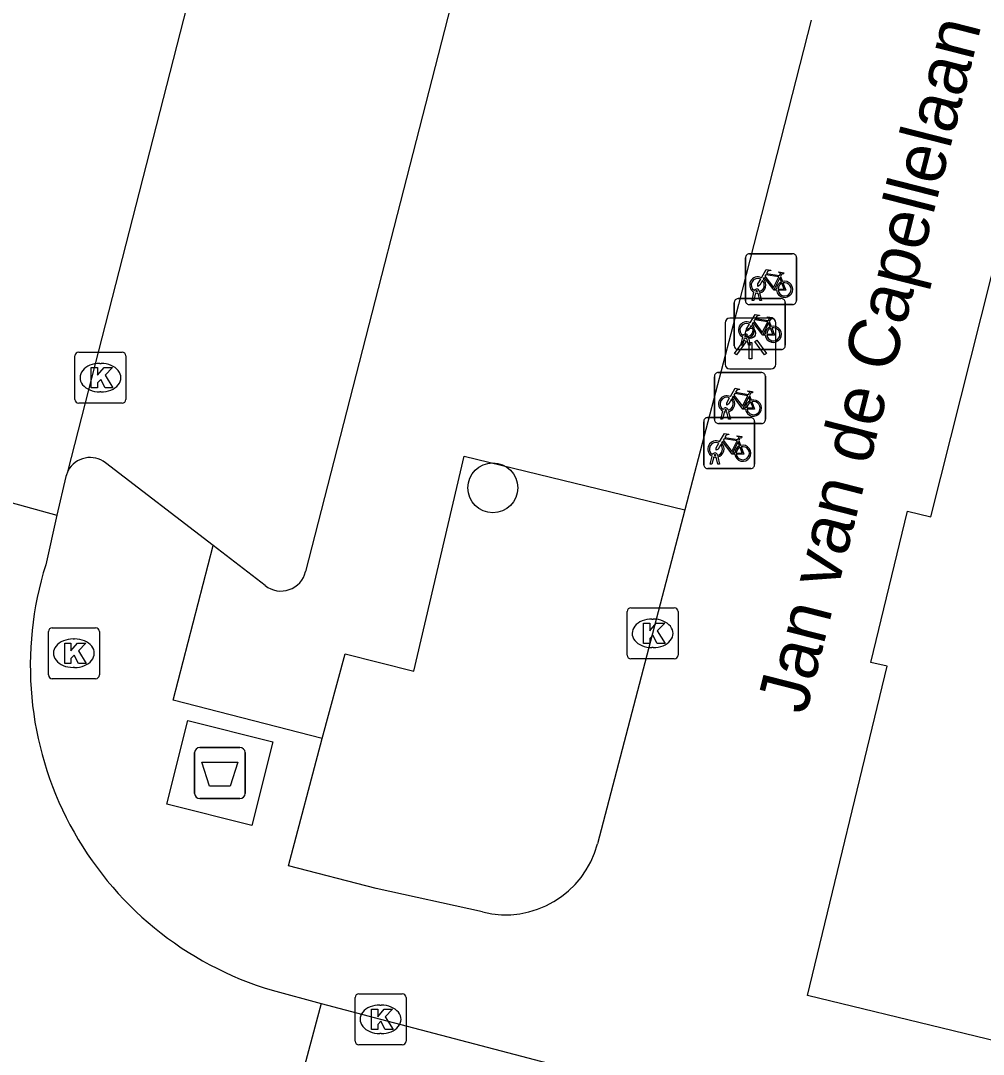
# Model space of a CAD drawing. Extents: x 163686 to 164493, y 382719 to 383870.
# Drawn here: x 164060.01 to 164078.91, y 383235.29 to 383255.57 of the extents above; entities that cross this region are included whole.
import ezdxf

# ---------------------------------------------------------------- set-up
doc = ezdxf.new("R2010")
doc.units = 0
for name, color, linetype in [('IMGEO_Afval_apart_plaats', 7, 'Continuous'), ('IMGEO_Boom', 7, 'Continuous'), ('IMGEO_Fietsenrek', 7, 'Continuous'), ('IMGEO_Groenvoorziening', 7, 'Continuous'), ('IMGEO_Kolk', 7, 'Continuous'), ('IMGEO_Lichtpunt', 7, 'Continuous'), ('IMGEO_Openbare_ruimte_label', 7, 'Continuous'), ('IMGEO_Pand', 7, 'Continuous'), ('IMGEO_Parkeervlak_open', 7, 'Continuous'), ('IMGEO_Rijbaan_lokaal_open', 7, 'Continuous'), ('IMGEO_Voetpad_gesloten', 7, 'Continuous'), ('IMGEO_Voetpad_open', 7, 'Continuous')]:
    doc.layers.add(name, color=color, linetype=linetype)

msp = doc.modelspace()

# ---------------------------------------------------------------- linework, layer by layer
at = {"layer": 'IMGEO_Afval_apart_plaats'}
for p, q in [((164063.428, 383240.407), (164063.428, 383241.207)), ((164063.428, 383241.207), (164063.428, 383240.407)), ((164063.528, 383241.307), (164064.318, 383241.307)), ((164064.318, 383241.307), (164063.528, 383241.307)), ((164064.418, 383241.207), (164064.418, 383240.407)), ((164064.418, 383240.407), (164064.418, 383241.207)), ((164064.318, 383240.307), (164063.528, 383240.307)), ((164063.528, 383240.307), (164064.318, 383240.307))]:
    msp.add_line(p, q, dxfattribs=at)
msp.add_lwpolyline([(164063.571, 383241.021), (164064.275, 383241.021), (164064.126, 383240.551), (164063.72, 383240.551), (164063.571, 383241.021)], dxfattribs=at)
for centre, start, end in [((164063.528, 383241.207), 90, 180), ((164063.528, 383241.207), 90, 180), ((164064.318, 383241.207), 0, 90), ((164064.318, 383241.207), 360, 90), ((164063.528, 383240.407), 180, 270), ((164063.528, 383240.407), 180, 270), ((164064.318, 383240.407), 270, 0), ((164064.318, 383240.407), 270, 0)]:
    msp.add_arc(centre, 0.1, start, end, dxfattribs=at)
at = {"layer": 'IMGEO_Boom'}
msp.add_circle((164069.28, 383246.4), 0.489, dxfattribs=at)
at = {"layer": 'IMGEO_Fietsenrek'}
for p, q in [((164074.315, 383250.995), (164075.156, 383250.995)), ((164075.156, 383250.995), (164074.315, 383250.995)), ((164074.24, 383250.07), (164074.24, 383250.911)), ((164074.24, 383250.911), (164074.24, 383250.07)), ((164075.24, 383250.92), (164075.24, 383250.079)), ((164075.24, 383250.079), (164075.24, 383250.92)), ((164074.927, 383250.544), (164074.963, 383250.449)), ((164074.367, 383250.079), (164074.406, 383250.239)), ((164074.436, 383250.227), (164074.401, 383250.079)), ((164074.478, 383250.251), (164074.477, 383250.255)), ((164074.519, 383250.079), (164074.485, 383250.221)), ((164074.509, 383250.262), (164074.51, 383250.255)), ((164074.517, 383250.225), (164074.552, 383250.079)), ((164074.019, 383249.188), (164074.019, 383250.029)), ((164074.019, 383250.029), (164074.019, 383249.188)), ((164074.094, 383250.113), (164074.935, 383250.113)), ((164074.935, 383250.113), (164074.094, 383250.113)), ((164075.165, 383249.995), (164074.324, 383249.995)), ((164074.324, 383249.995), (164075.165, 383249.995)), ((164074.401, 383250.079), (164074.367, 383250.079)), ((164074.552, 383250.079), (164074.519, 383250.079)), ((164075.019, 383250.038), (164075.019, 383249.197)), ((164075.019, 383249.197), (164075.019, 383250.038)), ((164074.706, 383249.662), (164074.742, 383249.567)), ((164074.146, 383249.197), (164074.185, 383249.357)), ((164074.215, 383249.345), (164074.18, 383249.197)), ((164074.257, 383249.369), (164074.256, 383249.373)), ((164074.298, 383249.197), (164074.264, 383249.339)), ((164074.288, 383249.38), (164074.289, 383249.373)), ((164074.296, 383249.343), (164074.331, 383249.197)), ((164074.18, 383249.197), (164074.146, 383249.197)), ((164074.331, 383249.197), (164074.298, 383249.197)), ((164074.944, 383249.113), (164074.103, 383249.113)), ((164074.103, 383249.113), (164074.944, 383249.113)), ((164073.63, 383247.739), (164073.63, 383248.58)), ((164073.63, 383248.58), (164073.63, 383247.739)), ((164073.705, 383248.664), (164074.546, 383248.664)), ((164074.546, 383248.664), (164073.705, 383248.664)), ((164074.63, 383248.589), (164074.63, 383247.748)), ((164074.63, 383247.748), (164074.63, 383248.589)), ((164074.317, 383248.213), (164074.353, 383248.118)), ((164073.757, 383247.748), (164073.796, 383247.908)), ((164073.868, 383247.92), (164073.867, 383247.924)), ((164073.899, 383247.931), (164073.9, 383247.924)), ((164073.419, 383246.854), (164073.419, 383247.695)), ((164073.419, 383247.695), (164073.419, 383246.854)), ((164073.494, 383247.779), (164074.335, 383247.779)), ((164074.335, 383247.779), (164073.494, 383247.779)), ((164073.791, 383247.748), (164073.757, 383247.748)), ((164073.826, 383247.896), (164073.791, 383247.748)), ((164073.909, 383247.748), (164073.875, 383247.89)), ((164073.907, 383247.894), (164073.942, 383247.748)), ((164073.942, 383247.748), (164073.909, 383247.748)), ((164074.419, 383247.704), (164074.419, 383246.863)), ((164074.419, 383246.863), (164074.419, 383247.704)), ((164074.555, 383247.664), (164073.714, 383247.664)), ((164073.714, 383247.664), (164074.555, 383247.664)), ((164074.106, 383247.328), (164074.142, 383247.233)), ((164073.546, 383246.863), (164073.585, 383247.023)), ((164073.615, 383247.011), (164073.58, 383246.863)), ((164073.657, 383247.035), (164073.656, 383247.039)), ((164073.698, 383246.863), (164073.664, 383247.005)), ((164073.688, 383247.046), (164073.689, 383247.039)), ((164073.696, 383247.009), (164073.731, 383246.863)), ((164074.344, 383246.779), (164073.503, 383246.779)), ((164073.503, 383246.779), (164074.344, 383246.779)), ((164073.58, 383246.863), (164073.546, 383246.863)), ((164073.731, 383246.863), (164073.698, 383246.863))]:
    msp.add_line(p, q, dxfattribs=at)
for points in [[(164074.553, 383250.521), (164074.648, 383250.685), (164074.734, 383250.671), (164074.736, 383250.662), (164074.68, 383250.651), (164074.653, 383250.606), (164074.909, 383250.565)], [(164074.896, 383250.54), (164074.639, 383250.581), (164074.622, 383250.552), (164074.789, 383250.332), (164074.896, 383250.54)], [(164074.909, 383250.565), (164074.934, 383250.614), (164074.928, 383250.618), (164074.905, 383250.622), (164074.893, 383250.629), (164074.892, 383250.632), (164074.894, 383250.637), (164074.989, 383250.622), (164074.991, 383250.612), (164074.981, 383250.599), (164074.969, 383250.593), (164074.955, 383250.599), (164074.927, 383250.544)], [(164074.574, 383250.469), (164074.522, 383250.379), (164074.482, 383250.354), (164074.483, 383250.401), (164074.538, 383250.495)], [(164074.849, 383250.277), (164074.799, 383250.277), (164074.608, 383250.528), (164074.589, 383250.496)], [(164074.944, 383250.442), (164074.914, 383250.519), (164074.805, 383250.301), (164074.848, 383250.301)], [(164074.878, 383250.301), (164074.998, 383250.3), (164074.954, 383250.414)], [(164074.974, 383250.421), (164075.029, 383250.276), (164074.879, 383250.276)], [(164074.332, 383249.639), (164074.427, 383249.803), (164074.513, 383249.789), (164074.515, 383249.78), (164074.459, 383249.769), (164074.432, 383249.724), (164074.688, 383249.683)], [(164074.688, 383249.683), (164074.713, 383249.732), (164074.707, 383249.736), (164074.684, 383249.74), (164074.672, 383249.747), (164074.671, 383249.75), (164074.673, 383249.755), (164074.768, 383249.74), (164074.77, 383249.73), (164074.76, 383249.717), (164074.748, 383249.711), (164074.734, 383249.717), (164074.706, 383249.662)], [(164074.353, 383249.587), (164074.301, 383249.497), (164074.261, 383249.472), (164074.262, 383249.519), (164074.317, 383249.613)], [(164074.628, 383249.395), (164074.578, 383249.395), (164074.387, 383249.646), (164074.368, 383249.614)], [(164074.675, 383249.658), (164074.418, 383249.699), (164074.401, 383249.67), (164074.568, 383249.45), (164074.675, 383249.658)], [(164074.723, 383249.56), (164074.693, 383249.637), (164074.584, 383249.419), (164074.627, 383249.419)], [(164074.657, 383249.419), (164074.777, 383249.418), (164074.733, 383249.532)], [(164074.753, 383249.539), (164074.808, 383249.394), (164074.658, 383249.394)], [(164073.943, 383248.19), (164074.038, 383248.354), (164074.124, 383248.34), (164074.126, 383248.331), (164074.07, 383248.32), (164074.043, 383248.275), (164074.299, 383248.234)], [(164074.299, 383248.234), (164074.324, 383248.283), (164074.318, 383248.287), (164074.295, 383248.291), (164074.283, 383248.298), (164074.282, 383248.301), (164074.284, 383248.306), (164074.379, 383248.291), (164074.381, 383248.281), (164074.371, 383248.268), (164074.359, 383248.262), (164074.345, 383248.268), (164074.317, 383248.213)], [(164073.964, 383248.138), (164073.912, 383248.048), (164073.872, 383248.023), (164073.873, 383248.07), (164073.928, 383248.164)], [(164074.239, 383247.946), (164074.189, 383247.946), (164073.998, 383248.197), (164073.979, 383248.165)], [(164074.286, 383248.209), (164074.029, 383248.25), (164074.012, 383248.221), (164074.179, 383248.001), (164074.286, 383248.209)], [(164074.334, 383248.111), (164074.304, 383248.188), (164074.195, 383247.97), (164074.238, 383247.97)], [(164074.268, 383247.97), (164074.388, 383247.969), (164074.344, 383248.083)], [(164074.364, 383248.09), (164074.419, 383247.945), (164074.269, 383247.945)], [(164073.732, 383247.305), (164073.827, 383247.469), (164073.913, 383247.455), (164073.915, 383247.446), (164073.859, 383247.435), (164073.832, 383247.39), (164074.088, 383247.349)], [(164074.028, 383247.061), (164073.978, 383247.061), (164073.787, 383247.312), (164073.768, 383247.28)], [(164074.075, 383247.324), (164073.818, 383247.365), (164073.801, 383247.336), (164073.968, 383247.116), (164074.075, 383247.324)], [(164074.123, 383247.226), (164074.093, 383247.303), (164073.984, 383247.085), (164074.027, 383247.085)], [(164074.088, 383247.349), (164074.113, 383247.398), (164074.107, 383247.402), (164074.084, 383247.406), (164074.072, 383247.413), (164074.071, 383247.416), (164074.073, 383247.421), (164074.168, 383247.406), (164074.17, 383247.396), (164074.16, 383247.383), (164074.148, 383247.377), (164074.134, 383247.383), (164074.106, 383247.328)], [(164073.753, 383247.253), (164073.701, 383247.163), (164073.661, 383247.138), (164073.662, 383247.185), (164073.717, 383247.279)], [(164074.057, 383247.085), (164074.177, 383247.084), (164074.133, 383247.198)], [(164074.153, 383247.205), (164074.208, 383247.06), (164074.058, 383247.06)]]:
    msp.add_lwpolyline(points, dxfattribs=at)
for centre, radius, start, end in [((164074.318, 383250.917), 0.0779, 92.4484, 184.2845), ((164074.318, 383250.917), 0.0779, 92.4484, 184.2845), ((164075.162, 383250.917), 0.0779, 2.4484, 94.2845), ((164075.162, 383250.917), 0.0779, 2.4484, 94.2845), ((164074.48, 383250.38), 0.159, 62.6766, 242.1369), ((164074.48, 383250.38), 0.129, 63.3192, 238.903), ((164074.48, 383250.38), 0.129, 283.6043, 43.4302), ((164074.48, 383250.38), 0.159, 283.5766, 46.6042), ((164075.007, 383250.296), 0.159, 113.3408, 178.3217), ((164075.007, 383250.296), 0.159, 187.0065, 105.7708), ((164075.007, 383250.296), 0.129, 113.923, 177.9556), ((164075.007, 383250.296), 0.129, 188.6715, 104.5883), ((164074.46, 383250.251), 0.0499, 12.8025, 158.6934), ((164074.48, 383250.38), 0.159, 253.9967, 271.7867), ((164074.46, 383250.251), 0.0174, 12.8025, 163.4502), ((164074.48, 383250.38), 0.129, 253.415, 269.0204), ((164074.097, 383250.035), 0.0779, 92.4484, 184.2845), ((164074.097, 383250.035), 0.0779, 92.4484, 184.2845), ((164074.318, 383250.073), 0.0779, 182.4484, 274.2845), ((164074.318, 383250.073), 0.0779, 182.4484, 274.2845), ((164074.941, 383250.035), 0.0779, 2.4484, 94.2845), ((164074.941, 383250.035), 0.0779, 2.4484, 94.2845), ((164075.162, 383250.073), 0.0779, 272.4484, 4.2845), ((164075.162, 383250.073), 0.0779, 272.4484, 4.2845), ((164074.259, 383249.498), 0.159, 62.6766, 242.1369), ((164074.259, 383249.498), 0.129, 63.3192, 238.903), ((164074.259, 383249.498), 0.129, 283.6043, 43.4302), ((164074.259, 383249.498), 0.159, 283.5766, 46.6042), ((164074.786, 383249.414), 0.159, 113.3408, 178.3217), ((164074.786, 383249.414), 0.159, 187.0065, 105.7708), ((164074.786, 383249.414), 0.129, 113.923, 177.9556), ((164074.786, 383249.414), 0.129, 188.6715, 104.5883), ((164074.239, 383249.369), 0.0499, 12.8025, 158.6934), ((164074.259, 383249.498), 0.159, 253.9967, 271.7867), ((164074.239, 383249.369), 0.0174, 12.8025, 163.4502), ((164074.259, 383249.498), 0.129, 253.415, 269.0204), ((164074.097, 383249.191), 0.0779, 182.4484, 274.2845), ((164074.097, 383249.191), 0.0779, 182.4484, 274.2845), ((164074.941, 383249.191), 0.0779, 272.4484, 4.2845), ((164074.941, 383249.191), 0.0779, 272.4484, 4.2845), ((164073.708, 383248.586), 0.0779, 92.4484, 184.2845), ((164073.708, 383248.586), 0.0779, 92.4484, 184.2845), ((164074.552, 383248.586), 0.0779, 2.4484, 94.2845), ((164074.552, 383248.586), 0.0779, 2.4484, 94.2845), ((164073.87, 383248.049), 0.159, 62.6766, 242.1369), ((164073.87, 383248.049), 0.129, 63.3192, 238.903), ((164073.87, 383248.049), 0.129, 283.6043, 43.4302), ((164073.87, 383248.049), 0.159, 283.5766, 46.6042), ((164074.397, 383247.965), 0.159, 113.3408, 178.3217), ((164074.397, 383247.965), 0.159, 187.0065, 105.7708), ((164073.85, 383247.92), 0.0499, 12.8025, 158.6934), ((164073.85, 383247.92), 0.0174, 12.8025, 163.4502), ((164073.87, 383248.049), 0.129, 253.415, 269.0204), ((164074.397, 383247.965), 0.129, 113.923, 177.9556), ((164074.397, 383247.965), 0.129, 188.6715, 104.5883), ((164073.497, 383247.701), 0.0779, 92.4484, 184.2845), ((164073.497, 383247.701), 0.0779, 92.4484, 184.2845), ((164073.708, 383247.742), 0.0779, 182.4484, 274.2845), ((164073.708, 383247.742), 0.0779, 182.4484, 274.2845), ((164073.87, 383248.049), 0.159, 253.9967, 271.7867), ((164074.341, 383247.701), 0.0779, 2.4484, 94.2845), ((164074.341, 383247.701), 0.0779, 2.4484, 94.2845), ((164074.552, 383247.742), 0.0779, 272.4484, 4.2845), ((164074.552, 383247.742), 0.0779, 272.4484, 4.2845), ((164073.659, 383247.164), 0.159, 62.6766, 242.1369), ((164073.659, 383247.164), 0.129, 63.3192, 238.903), ((164073.659, 383247.164), 0.129, 283.6043, 43.4302), ((164073.659, 383247.164), 0.159, 283.5766, 46.6042), ((164074.186, 383247.08), 0.159, 113.3408, 178.3217), ((164074.186, 383247.08), 0.159, 187.0065, 105.7708), ((164074.186, 383247.08), 0.129, 113.923, 177.9556), ((164074.186, 383247.08), 0.129, 188.6715, 104.5883), ((164073.639, 383247.035), 0.0499, 12.8025, 158.6934), ((164073.659, 383247.164), 0.159, 253.9967, 271.7867), ((164073.639, 383247.035), 0.0174, 12.8025, 163.4502), ((164073.659, 383247.164), 0.129, 253.415, 269.0204), ((164073.497, 383246.857), 0.0779, 182.4484, 274.2845), ((164073.497, 383246.857), 0.0779, 182.4484, 274.2845), ((164074.341, 383246.857), 0.0779, 272.4484, 4.2845), ((164074.341, 383246.857), 0.0779, 272.4484, 4.2845)]:
    msp.add_arc(centre, radius, start, end, dxfattribs=at)
at = {"layer": 'IMGEO_Groenvoorziening'}
msp.add_lwpolyline([(164065.931, 383241.485), (164066.381, 383243.145), (164067.727, 383242.806), (164068.72, 383247.025), (164073.047, 383245.968)], dxfattribs=at)
at = {"layer": 'IMGEO_Kolk'}
for p, q in [((164061.078, 383248.136), (164061.078, 383248.988)), ((164061.153, 383249.062), (164062.005, 383249.062)), ((164062.079, 383248.988), (164062.079, 383248.136)), ((164061.566, 383248.842), (164061.591, 383248.842)), ((164061.589, 383248.282), (164061.564, 383248.282)), ((164062.005, 383248.062), (164061.153, 383248.062)), ((164071.99, 383244.047), (164072.842, 383244.047)), ((164071.915, 383243.121), (164071.915, 383243.973)), ((164072.916, 383243.973), (164072.916, 383243.121)), ((164060.632, 383243.657), (164061.484, 383243.657)), ((164072.403, 383243.827), (164072.428, 383243.827)), ((164060.557, 383242.731), (164060.557, 383243.583)), ((164061.045, 383243.437), (164061.07, 383243.437)), ((164061.558, 383243.583), (164061.558, 383242.731)), ((164072.426, 383243.267), (164072.401, 383243.267)), ((164072.842, 383243.047), (164071.99, 383243.047)), ((164061.068, 383242.877), (164061.043, 383242.877)), ((164061.484, 383242.657), (164060.632, 383242.657)), ((164066.576, 383235.549), (164066.576, 383236.401)), ((164066.651, 383236.475), (164067.503, 383236.475)), ((164067.577, 383236.401), (164067.577, 383235.549)), ((164067.064, 383236.255), (164067.089, 383236.255)), ((164067.087, 383235.695), (164067.062, 383235.695)), ((164067.503, 383235.475), (164066.651, 383235.475))]:
    msp.add_line(p, q, dxfattribs=at)
for points in [[(164061.078, 383248.136), (164061.078, 383248.988)], [(164061.153, 383249.062), (164062.005, 383249.062)], [(164062.079, 383248.988), (164062.079, 383248.136)], [(164061.399, 383248.762), (164061.522, 383248.762), (164061.522, 383248.611), (164061.652, 383248.762), (164061.816, 383248.762), (164061.67, 383248.611), (164061.823, 383248.362), (164061.671, 383248.362), (164061.586, 383248.526), (164061.522, 383248.459), (164061.522, 383248.362), (164061.399, 383248.362), (164061.399, 383248.762)], [(164062.005, 383248.062), (164061.153, 383248.062)], [(164071.99, 383244.047), (164072.842, 383244.047)], [(164071.915, 383243.121), (164071.915, 383243.973)], [(164072.916, 383243.973), (164072.916, 383243.121)], [(164060.632, 383243.657), (164061.484, 383243.657)], [(164072.236, 383243.747), (164072.359, 383243.747), (164072.359, 383243.596), (164072.489, 383243.747), (164072.653, 383243.747), (164072.507, 383243.596), (164072.66, 383243.347), (164072.508, 383243.347), (164072.423, 383243.511), (164072.359, 383243.444), (164072.359, 383243.347), (164072.236, 383243.347), (164072.236, 383243.747)], [(164060.557, 383242.731), (164060.557, 383243.583)], [(164061.558, 383243.583), (164061.558, 383242.731)], [(164060.878, 383243.357), (164061.001, 383243.357), (164061.001, 383243.206), (164061.131, 383243.357), (164061.295, 383243.357), (164061.149, 383243.206), (164061.302, 383242.957), (164061.15, 383242.957), (164061.065, 383243.121), (164061.001, 383243.054), (164061.001, 383242.957), (164060.878, 383242.957), (164060.878, 383243.357)], [(164072.842, 383243.047), (164071.99, 383243.047)], [(164061.484, 383242.657), (164060.632, 383242.657)], [(164066.576, 383235.549), (164066.576, 383236.401)], [(164066.651, 383236.475), (164067.503, 383236.475)], [(164067.577, 383236.401), (164067.577, 383235.549)], [(164066.897, 383236.175), (164067.02, 383236.175), (164067.02, 383236.024), (164067.15, 383236.175), (164067.314, 383236.175), (164067.168, 383236.024), (164067.321, 383235.775), (164067.169, 383235.775), (164067.084, 383235.939), (164067.02, 383235.872), (164067.02, 383235.775), (164066.897, 383235.775), (164066.897, 383236.175)], [(164067.503, 383235.475), (164066.651, 383235.475)]]:
    msp.add_lwpolyline(points, dxfattribs=at)
for centre, start, end in [((164061.155, 383248.986), 91.552, 178.448), ((164061.155, 383248.986), 91.552, 178.448), ((164062.003, 383248.986), 1.552, 88.448), ((164062.003, 383248.986), 1.552, 88.448), ((164061.155, 383248.138), 181.552, 268.448), ((164061.155, 383248.138), 181.552, 268.448), ((164062.003, 383248.138), 271.552, 358.448), ((164062.003, 383248.138), 271.552, 358.448), ((164071.992, 383243.971), 91.552, 178.448), ((164071.992, 383243.971), 91.552, 178.448), ((164072.84, 383243.971), 1.552, 88.448), ((164072.84, 383243.971), 1.552, 88.448), ((164060.634, 383243.581), 91.552, 178.448), ((164060.634, 383243.581), 91.552, 178.448), ((164061.482, 383243.581), 1.552, 88.448), ((164061.482, 383243.581), 1.552, 88.448), ((164071.992, 383243.123), 181.552, 268.448), ((164071.992, 383243.123), 181.552, 268.448), ((164072.84, 383243.123), 271.552, 358.448), ((164072.84, 383243.123), 271.552, 358.448), ((164060.634, 383242.733), 181.552, 268.448), ((164060.634, 383242.733), 181.552, 268.448), ((164061.482, 383242.733), 271.552, 358.448), ((164061.482, 383242.733), 271.552, 358.448), ((164066.653, 383236.399), 91.552, 178.448), ((164066.653, 383236.399), 91.552, 178.448), ((164067.501, 383236.399), 1.552, 88.448), ((164067.501, 383236.399), 1.552, 88.448), ((164066.653, 383235.551), 181.552, 268.448), ((164066.653, 383235.551), 181.552, 268.448), ((164067.501, 383235.551), 271.552, 358.448), ((164067.501, 383235.551), 271.552, 358.448)]:
    msp.add_arc(centre, 0.0765, start, end, dxfattribs=at)
for centre, major_axis, ratio, start_param, end_param in [((164061.565, 383248.562), (-0.387, 0.002), 0.722429, 4.712389, 7.853982), ((164061.59, 383248.562), (-0.39, 0.002), 0.717154, 1.570796, 4.712389), ((164072.402, 383243.547), (-0.387, 0.002), 0.722429, 4.712389, 7.853982), ((164072.427, 383243.547), (-0.39, 0.002), 0.717154, 1.570796, 4.712389), ((164061.044, 383243.157), (-0.387, 0.002), 0.722429, 4.712389, 7.853982), ((164061.069, 383243.157), (-0.39, 0.002), 0.717154, 1.570796, 4.712389), ((164067.063, 383235.975), (-0.387, 0.002), 0.722429, 4.712389, 7.853982), ((164067.088, 383235.975), (-0.39, 0.002), 0.717154, 1.570796, 4.712389)]:
    msp.add_ellipse(centre, major_axis=major_axis, ratio=ratio, start_param=start_param, end_param=end_param, dxfattribs=at)
at = {"layer": 'IMGEO_Lichtpunt'}
for p, q in [((164074.74, 383249.73), (164073.932, 383249.73)), ((164074.74, 383249.73), (164073.932, 383249.73)), ((164073.838, 383249.635), (164073.838, 383248.828)), ((164073.838, 383249.635), (164073.838, 383248.828)), ((164074.834, 383248.828), (164074.834, 383249.635)), ((164074.834, 383248.828), (164074.834, 383249.635)), ((164073.932, 383248.734), (164074.74, 383248.734)), ((164073.932, 383248.734), (164074.74, 383248.734))]:
    msp.add_line(p, q, dxfattribs=at)
for points in [[(164074.212, 383249.299), (164074.251, 383249.271), (164074.063, 383249.009), (164074.025, 383249.036), (164074.212, 383249.299)], [(164074.314, 383249.251), (164074.361, 383249.251), (164074.361, 383248.929), (164074.314, 383248.929), (164074.314, 383249.251)], [(164074.424, 383249.271), (164074.462, 383249.298), (164074.649, 383249.036), (164074.61, 383249.008), (164074.424, 383249.271)]]:
    msp.add_lwpolyline(points, dxfattribs=at)
msp.add_circle((164074.337, 383249.433), 0.0994, dxfattribs=at)
for centre, start, end in [((164073.932, 383249.635), 90, 180), ((164073.932, 383249.635), 90, 180), ((164074.74, 383249.635), 0, 90), ((164074.74, 383249.635), 0, 90), ((164073.932, 383248.828), 180, 270), ((164073.932, 383248.828), 180, 270), ((164074.74, 383248.828), 270, 0), ((164074.74, 383248.828), 270, 360)]:
    msp.add_arc(centre, 0.0946, start, end, dxfattribs=at)
at = {"layer": 'IMGEO_Pand'}
msp.add_lwpolyline([(164087.976, 383238.019), (164086.89, 383233.668), (164075.456, 383236.441), (164077.023, 383242.901), (164076.702, 383242.978), (164077.42, 383245.941), (164077.875, 383245.831), (164079.651, 383252.859)], dxfattribs=at)
at = {"layer": 'IMGEO_Parkeervlak_open'}
for points in [[(164068.832, 383257.319), (164065.605, 383244.758)], [(164064.813, 383244.484), (164063.789, 383245.271)]]:
    msp.add_lwpolyline(points, dxfattribs=at)
msp.add_arc((164065.122, 383244.874), 0.497, 231.6401, 346.527, dxfattribs=at)
at = {"layer": 'IMGEO_Rijbaan_lokaal_open'}
for points in [[(164060.947, 383246.741), (164064.817, 383261.854)], [(164056.84, 383246.936), (164060.726, 383245.862)], [(164060.947, 383246.741), (164060.9, 383246.621), (164060.726, 383245.862)], [(164060.726, 383245.862), (164060.505, 383244.894)], [(164064.95, 383236.545), (164065.911, 383236.287)], [(164065.911, 383236.287), (164064.885, 383232.449)], [(164065.911, 383236.287), (164067.077, 383235.975), (164085.996, 383231.014)]]:
    msp.add_lwpolyline(points, dxfattribs=at)
msp.add_arc((164066.844, 383242.911), 6.642, 162.6327, 253.4289, dxfattribs=at)
at = {"layer": 'IMGEO_Voetpad_gesloten'}
msp.add_lwpolyline([(164064.962, 383241.416), (164064.552, 383239.78), (164062.884, 383240.198), (164063.294, 383241.834), (164064.962, 383241.416)], dxfattribs=at)
at = {"layer": 'IMGEO_Voetpad_open'}
for points in [[(164075.528, 383255.575), (164074.102, 383250), (164073.047, 383245.968)], [(164063.789, 383245.271), (164061.676, 383246.894)], [(164073.047, 383245.968), (164071.333, 383239.419)], [(164065.931, 383241.485), (164063.009, 383242.239), (164063.789, 383245.271)], [(164069.077, 383238.082), (164066.988, 383238.54), (164065.27, 383238.985), (164065.931, 383241.485)]]:
    msp.add_lwpolyline(points, dxfattribs=at)
for centre, radius, start, end in [((164061.377, 383246.505), 0.491, 52.4782, 151.2278), ((164069.533, 383239.884), 1.859, 255.7983, 345.5072)]:
    msp.add_arc(centre, radius, start, end, dxfattribs=at)

# ---------------------------------------------------------------- texts
at = {"layer": 'IMGEO_Openbare_ruimte_label'}
msp.add_text('Jan van de Capellelaan', height=1, rotation=75.6997, dxfattribs=at).set_placement((164075.421, 383241.934))
msp.add_text('Jan van de Capellelaan', height=1, rotation=75.6997, dxfattribs=at).set_placement((164075.421, 383241.934))

doc.saveas('drawing.dxf')
